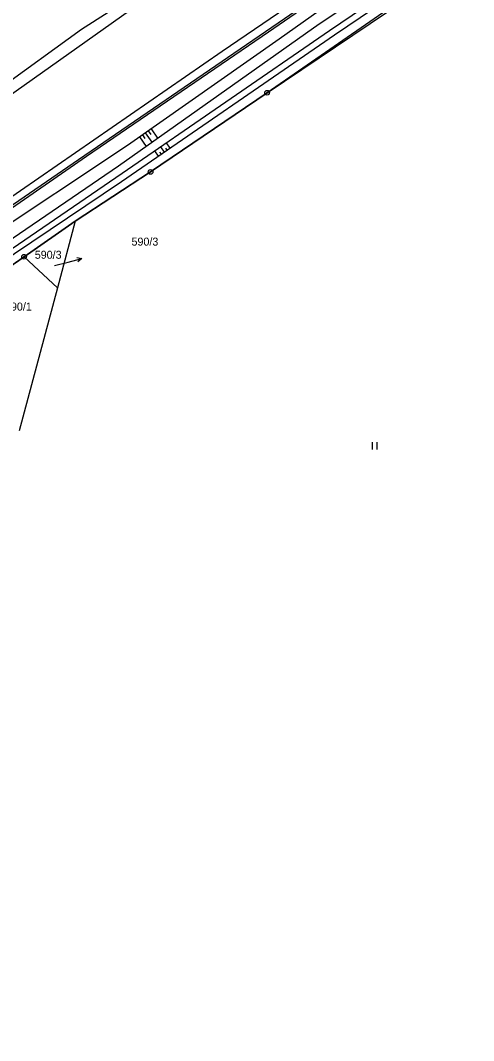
# Model space of a CAD drawing. Extents: x -469926 to -462499, y -1098642 to -1092733.
# Drawn here: x -467702.3 to -467606.1, y -1097219.1 to -1097002.4 of the extents above; entities that cross this region are included whole.
import ezdxf

# ---------------------------------------------------------------- set-up
doc = ezdxf.new("R2010")
doc.units = 0
for name, color, linetype in [('Vrstva 1', 7, 'Continuous'), ('Vrstva 10', 7, 'Continuous'), ('Vrstva 13', 7, 'Continuous'), ('Vrstva 16', 7, 'Continuous'), ('Vrstva 20', 7, 'Continuous'), ('Vrstva 24', 7, 'Continuous'), ('Vrstva 25', 7, 'Continuous'), ('Vrstva 44', 7, 'Continuous'), ('Vrstva 46', 7, 'Continuous'), ('Vrstva 48', 7, 'Continuous'), ('Vrstva 50', 7, 'Continuous'), ('Vrstva 51', 7, 'Continuous'), ('Vrstva 58', 7, 'Continuous'), ('Vrstva 62', 7, 'Continuous')]:
    doc.layers.add(name, color=color, linetype=linetype)

msp = doc.modelspace()

# ---------------------------------------------------------------- linework, layer by layer
at = {"layer": 'Vrstva 1'}
for p, q in [((-467649.9, -1097017.76), (-467624.34, -1097000.54)), ((-467674.64, -1097034.59), (-467649.9, -1097017.76)), ((-467690.63, -1097045.08), (-467674.64, -1097034.59)), ((-467701.48, -1097052.6), (-467690.63, -1097045.08)), ((-467690.63, -1097045.08), (-467694.41, -1097059.22)), ((-467724.66, -1097068.66), (-467701.48, -1097052.6)), ((-467701.48, -1097052.6), (-467694.41, -1097059.22)), ((-467694.41, -1097059.22), (-467702.53, -1097089.6))]:
    msp.add_line(p, q, dxfattribs=at)
at = {"layer": 'Vrstva 10'}
msp.add_lwpolyline([(-467598.73, -1096982.29), (-467649.9, -1097017.76), (-467674.64, -1097034.59), (-467690.63, -1097045.08), (-467701.48, -1097052.6), (-467724.66, -1097068.66), (-467747.92, -1097084.78), (-467770.93, -1097100.72), (-467793.76, -1097116.47), (-467815.79, -1097131.29), (-467870.41, -1097169.38), (-467873.68, -1097171.54), (-467876.44, -1097173.68), (-467891.79, -1097184.36), (-467920.81, -1097204.53), (-467935.93, -1097215.1), (-467938.26, -1097219.13)], dxfattribs=at)
at = {"layer": 'Vrstva 13'}
msp.add_lwpolyline([(-467900, -1097180.6), (-467897.17, -1097176.71), (-467889.34, -1097169.18), (-467875.61, -1097159.42), (-467858.94, -1097148.38), (-467843.47, -1097138.96), (-467822.08, -1097123.44), (-467793.53, -1097103.7), (-467762.79, -1097082.62), (-467723.39, -1097055.6), (-467688.2, -1097031.21), (-467649.59, -1097004.79), (-467608.42, -1096976.41)], dxfattribs=at)
at = {"layer": 'Vrstva 16'}
for p, q in [((-467695.02, -1097054.49), (-467692.12, -1097053.72)), ((-467692.12, -1097053.72), (-467689.22, -1097052.95))]:
    msp.add_line(p, q, dxfattribs=at)
msp.add_lwpolyline([(-467690.31, -1097052.73), (-467689.22, -1097052.95), (-467690.06, -1097053.69)], dxfattribs=at)
at = {"layer": 'Vrstva 20'}
msp.add_lwpolyline([(-467898.53, -1097177.25), (-467898.92, -1097172.7), (-467750.16, -1097071.31), (-467710.1, -1097043.92), (-467659.44, -1097008.91), (-467601.25, -1096969.18), (-467576.17, -1096956.63), (-467559.87, -1096944.52), (-467546.18, -1096931.64), (-467506.1, -1096903.82), (-467451.19, -1096865.6), (-467389.34, -1096822.85), (-467331.14, -1096782.86), (-467269.83, -1096740.82), (-467245.75, -1096727.72), (-467237.39, -1096726.88), (-467228.65, -1096727.98), (-467203.72, -1096744.02), (-467183.73, -1096749.88), (-467175.02, -1096748.65), (-467161.6, -1096742.85), (-467144.51, -1096733.78)], dxfattribs=at)
at = {"layer": 'Vrstva 24'}
for centre, radius in [((-467649.9, -1097017.76), 0.5), ((-467649.9, -1097017.76), 0.1), ((-467674.64, -1097034.59), 0.5), ((-467674.64, -1097034.59), 0.1), ((-467701.48, -1097052.6), 0.5), ((-467701.48, -1097052.6), 0.1)]:
    msp.add_circle(centre, radius, dxfattribs=at)
at = {"layer": 'Vrstva 25'}
for p, q in [((-467627.64, -1097092.02), (-467627.64, -1097093.52)), ((-467626.64, -1097092.02), (-467626.64, -1097093.52))]:
    msp.add_line(p, q, dxfattribs=at)
at = {"layer": 'Vrstva 44'}
for p, q in [((-467689.92, -1097031.93), (-467596.36, -1096967.75)), ((-467813.71, -1097116.75), (-467689.92, -1097031.93))]:
    msp.add_line(p, q, dxfattribs=at)
at = {"layer": 'Vrstva 46'}
msp.add_line((-467763.03, -1097059.8), (-467659.81, -1096986.55), dxfattribs=at)
at = {"layer": 'Vrstva 48'}
for points in [[(-467675.77, -1097026.27), (-467674.35, -1097028.28)], [(-467675.16, -1097025.83), (-467674.59, -1097026.64)], [(-467674.54, -1097025.4), (-467673.13, -1097027.42)], [(-467677, -1097027.13), (-467675.58, -1097029.15)], [(-467676.38, -1097026.7), (-467675.82, -1097027.51)], [(-467670.47, -1097029.55), (-467671.25, -1097028.42)], [(-467672.94, -1097031.26), (-467673.72, -1097030.12)], [(-467672.32, -1097030.83), (-467672.64, -1097030.38)], [(-467671.71, -1097030.4), (-467672.48, -1097029.27)], [(-467671.09, -1097029.98), (-467671.4, -1097029.53)]]:
    msp.add_lwpolyline(points, dxfattribs=at)
at = {"layer": 'Vrstva 51'}
for p, q in [((-467689.29, -1097004.23), (-467670.55, -1096992.23)), ((-467714.99, -1097022.85), (-467689.29, -1097004.23))]:
    msp.add_line(p, q, dxfattribs=at)
at = {"layer": 'Vrstva 58'}
msp.add_lwpolyline([(-467898.53, -1097177.25), (-467898.92, -1097172.7), (-467750.16, -1097071.31), (-467710.1, -1097043.92), (-467659.44, -1097008.91), (-467601.25, -1096969.18), (-467576.17, -1096956.63), (-467559.87, -1096944.52), (-467546.18, -1096931.64), (-467506.1, -1096903.82), (-467451.19, -1096865.6), (-467389.34, -1096822.85), (-467331.14, -1096782.86), (-467269.83, -1096740.82), (-467245.75, -1096727.72), (-467237.39, -1096726.88), (-467228.65, -1096727.98), (-467203.72, -1096744.02)], dxfattribs=at)
at = {"layer": 'Vrstva 62'}
for points in [[(-467900, -1097189.6), (-467894.24, -1097182.87), (-467882.83, -1097172.91), (-467869.21, -1097162.52), (-467845.95, -1097146.5), (-467804.95, -1097118.93), (-467758.24, -1097086.54), (-467716.62, -1097057.29), (-467681.46, -1097033.32), (-467638.85, -1097003.12), (-467602.19, -1096978.67)], [(-467601.24, -1096980.54), (-467636.68, -1097004.58), (-467680.68, -1097034.92), (-467715.73, -1097058.9), (-467757.14, -1097087.33), (-467804.1, -1097119.81), (-467845.84, -1097148.27), (-467871.48, -1097165.62), (-467881.85, -1097173.64), (-467885.08, -1097176.19), (-467892.71, -1097183.28), (-467900, -1097191.69)], [(-467599.91, -1096981.34), (-467635.57, -1097005.53), (-467680.79, -1097036.66), (-467715.02, -1097059.71), (-467756.65, -1097088.13), (-467804.06, -1097120.62), (-467845.86, -1097149.5), (-467873.73, -1097168.23), (-467884.8, -1097176.9), (-467891.81, -1097183.48), (-467900, -1097194.03)], [(-467900, -1097186), (-467891.99, -1097177.18), (-467881.68, -1097168.02), (-467865.48, -1097155.8), (-467846.47, -1097143.77), (-467829.81, -1097132.13), (-467789.04, -1097103.58), (-467743.45, -1097072.34), (-467710.23, -1097049.32), (-467679.52, -1097028.9), (-467647.36, -1097006.29), (-467617.98, -1096985.44)]]:
    msp.add_lwpolyline(points, dxfattribs=at)

# ---------------------------------------------------------------- texts
at = {"layer": 'Vrstva 50'}
for s, p in [('590/3', (-467678.68, -1097050.24)), ('590/3', (-467699.21, -1097053.03)), ('590/1', (-467705.53, -1097064.04))]:
    msp.add_text(s, height=1.7, dxfattribs=at).set_placement(p)

doc.saveas('drawing.dxf')
